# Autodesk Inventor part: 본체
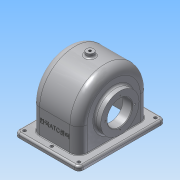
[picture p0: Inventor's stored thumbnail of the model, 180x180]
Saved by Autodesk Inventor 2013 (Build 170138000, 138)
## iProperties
Created: 2015-09
Part Number: 본체
Material: 알루미늄 6061
Document SubType Name: Modeling
Designer: semtle
Density: 2.71 g/cm^3
Mass: 690.142 g
Surface Area: 895.532 cm^2
Volume: 254.665 cm^3
Author: semtle
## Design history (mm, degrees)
sketch "스케치1"
  geometry: L1 (-52, 70)-(52, 70); L2 (52, 70)-(52, -70); L3 (52, -70)-(-52, -70); L4 (-52, -70)-(-52, 70); 1 further point
  constraints: 8 end point, 2 parallel, 1 horizontal, 1 perpendicular
  dimensions: "d0" = 140 distance between parallel lines of L3 L1; "d2" = 70 distance from line of point (0, 0) L1; "d3" = 104 distance between parallel lines of L2 L4; "d4" = 52 distance from line of point (0, 0) L4
extrude "돌출1" new body sketch "스케치1" distance "d5" = 7; taper "d6" = 0 deg
sketch "스케치2"
  geometry: 1 further point
sketch "스케치3"
  geometry: L1 (52, 7)-(-52, 7) reference; L2 (0, 47)-(0, 7); L3 (-52, 0)-(52, 0) reference; 1 further point
  constraints: 2 end point, 1 midpoint, 1 perpendicular
  dimensions: "d9" = 0 distance from line of point (0, 0) L2
sketch "스케치4"
  geometry: L1 (-70, 7)-(70, 7) reference; L2 (-70, 47)-(70, 47); L3 (70, 0)-(-70, 0) reference; L4 (0, 47)-(0, 0); L5 (-57, 47)-(-57, 7); L6 (57, 47)-(57, 7); A1 r 57 centre (0, 47) between (57, 47) and (-57, 47); 4 further points
  constraints: 8 end point, 8 point on line, 2 parallel, 2 perpendicular, 2 point on circle, 2 tangent, 1 centre point, 1 coincident, 1 midpoint
  dimensions: "d11" = 47 distance between parallel lines of L3 L2; "d18" = 57 radius of A1
extrude "돌출2" join sketch "스케치4" stored distance "d15" = 77; taper "d16" = 0 deg
fillet "모깎기1" dims "d19" = 14
fillet "모깎기2" dims "d20" = 7
sketch "스케치5"
  geometry: C1 r 31 at (-47, 0); A1 r 43 centre (-47, 0) between (-47, 43) and (-47, -43) reference; 1 further point
  constraints: 1 centre point, 1 coincident
  dimensions: "d21" = 62 diameter of C1
extrude "돌출3" join sketch "스케치5" distance "d23" = 10; taper "d24" = 0 deg
sketch "스케치6"
  geometry: C1 r 31 at (0, 0) reference; C2 r 20 at (0, 0); 1 further point
  constraints: 1 centre point, 1 coincident
  dimensions: "d25" = 40 diameter of C2
extrude "돌출4" cut sketch "스케치6" distance "d27" = 20; taper "d28" = 0 deg
node "작업 평면1"
node "작업 평면2"
sketch "스케치7"
  geometry: L1 (-14, 0)-(-14, 43) reference; L2 (-14, -40)-(-14, 0) reference; L3 (63, 43)-(63, 0) reference; L4 (63, 0)-(63, -40) reference; L5 (-14, 0)-(63, 0); L6 (0, 57)-(49, 57) reference; L7 (0, 0)-(-14, 0) reference; L8 (-14, 0)-(-14, 0) reference; L9 (0, 0)-(-14, 0) reference; L10 (0, 0)-(0, 0) reference; L11 (-14, -40)-(63, -40); L12 (58.385, 43)-(58.385, 0); L13 (58.385, 0)-(58.385, -35.385); L14 (58.385, -35.385)-(-9.385, -35.385); L15 (-9.385, -35.385)-(-9.385, 0); L16 (-9.385, 0)-(-9.385, 43); A1 r 14 centre (49, 43) between (63, 43) and (49, 57) reference; A2 r 14 centre (0, 43) between (0, 57) and (-14, 43) reference; A3 r 9.967 centre (49, 43) between (58.967, 43) and (49, 52.967); 1 further point
  constraints: 14 end point, 2 point on circle, 1 centre point, 1 parallel, 1 perpendicular, 4 other
  node "투영된 루프1"
sketch "스케치8"
  geometry: C1 r 33 at (47, 0); A1 r 43 centre (47, 0) between (47, -43) and (47, 43) reference; 1 further point
  constraints: 1 centre point, 1 coincident
  dimensions: "d29" = 66 diameter of C1
extrude "돌출5" cut sketch "스케치8" distance "d31" = 5; taper "d32" = 0 deg
sketch "스케치9"
  geometry: C1 r 33 at (0, 0) reference; C2 r 20 at (0, 0); 1 further point
  constraints: 1 centre point, 1 coincident
  dimensions: "d33" = 40 diameter of C2
extrude "돌출6" cut sketch "스케치9" distance "d36" = 16; taper "d37" = 0 deg
sketch "스케치10"
  geometry: L1 (38.5, 80)-(38.5, 14) reference; L2 (-48.5, 78)-(-48.5, 16) reference; L3 (38.5, 47)-(-48.5, 47); L4 (33.5, 27)-(17.5, 27) reference; L5 (-45, 7)-(45, 7) reference; L6 (17.5, 27)-(17.5, 15.895); L7 (33.5, 80)-(33.5, 14) reference; L8 (33.5, 14)-(33.5, 7); L9 (17.5, 15.895)-(33.5, 7); L10 (-28.5, 27)-(-28.5, 67) reference; 1 further point
  constraints: 8 end point, 2 midpoint, 2 perpendicular, 1 point on line
revolve "회전1" sketch "스케치10" stored, may be unused: angle "d38" = 90 deg
sketch "스케치11"
  geometry: L1 (57, 47)-(57, 7) reference; L2 (-57, 7)-(-57, 47) reference; L3 (63, 0)-(63, 7) reference; L4 (-63, 0)-(63, 0) reference; L5 (-63, 7)-(-63, 0) reference; L6 (63, 7)-(-63, 7) reference; L7 (-52, 7)-(-52, 47); L8 (52, 47)-(52, 7); A1 r 57 centre (0, 47) between (57, 47) and (-57, 47) reference; A2 r 52 centre (0, 47) between (52, 47) and (-52, 47); 1 further point
  constraints: 4 end point, 2 point on circle, 1 centre point, 2 other
  dimensions: "d39" = 5 radial gap between concentric circles of A2 A1
extrude "돌출7" cut sketch "스케치11" stored distance "d41" = 67; taper "d42" = 0 deg
fillet "모깎기3" dims "d43" = 9
sketch "스케치12"
  geometry: L1 (33.5, 80)-(33.5, 14) reference; L2 (-45, 7)-(45, 7) reference; L3 (33.5, 27)-(19.199, 27); L4 (19.199, 27)-(19.199, 19); L5 (19.199, 19)-(33.5, 7); L6 (33.5, 27)-(33.5, 7); L7 (-33.5, 27)-(-33.5, 67) reference; L8 (33.5, 47)-(-33.5, 47); 1 further point
  constraints: 10 end point, 2 midpoint, 2 point on line, 1 collinear, 1 parallel, 1 perpendicular
  dimensions: "d44" = 56 diameter of L4.end L8; "d46" = 50 deg angle of L5 L4; "d48" = 40 diameter of L3 L8
revolve "회전2" sketch "스케치12" stored, may be unused: angle "d49" = 90 deg
fillet "모깎기4" dims "d50" = 3
chamfer "모따기1" distance "d51" = 1; stored, may be unused: second distance "d52" = 2, angle "d53" = 45 deg
node "작업 평면3"
sketch "스케치13"
  geometry: C1 r 6 at (0, 0); 1 further point
  constraints: 1 centre point, 1 coincident
  dimensions: "d55" = 12 diameter of C1
extrude "돌출8" join sketch "스케치13" stored distance "d57" = 66; taper "d58" = 0 deg
sketch "스케치14"
  geometry: C1 r 6 at (0, 0) reference; C2 r 2.5 at (0, 0)
  constraints: 1 centre point, 1 coincident
  dimensions: "d59" = 5 diameter of C2
hole "구멍1" sketch "스케치14" at (0, 0) diameter "d61" = 4.134; stored, may be unused: countersink angle "d65" = 90 deg, drill point angle "d67" = 118 deg; dims "d62" = 6, "d63" = 4, "d64" = 2, "d66" = 8
fillet "모깎기5" dims "d68" = 3
fillet "모깎기6" dims "d69" = 1
sketch "스케치15"
  geometry: L1 (-0.387, -13.398)-(49.387, -13.398); L2 (49.387, -13.398)-(49.387, -20.602); L3 (49.387, -20.602)-(-0.387, -20.602); L4 (-0.387, -20.602)-(-0.387, -13.398); L5 (-0.387, -17)-(49.387, -17); L6 (24.5, -13.398)-(24.5, -20.602); L7 (-14, 0)-(-14, -39) reference; L8 (69.5, -47)-(-20.5, -47) reference; 1 further point
  constraints: 4 end point, 4 midpoint, 2 other
  dimensions: "d70" = 38.5 distance between parallel lines of L6 L7; "d71" = 30 distance between parallel lines of L5 L8
feature "엠보싱1" sketch "스케치15" dims "d11" = 47, "d18" = 57, "d72" = 0.5, "d73" = 0
sketch "스케치16"
  geometry: C1 r 2.5 at (-44, 62); C2 r 2.5 at (0, 62); C3 r 2.5 at (44, 62); C4 r 2.5 at (44, -62); C5 r 2.5 at (0, -62); C6 r 2.5 at (-44, -62); 1 further point
  constraints: 6 centre point, 5 equal radius
  dimensions: "d74" = 5 diameter of C1; "d76" = 0 horizontal distance of C6.centre C1.centre; "d77" = 124 distance of C6.centre C1.centre; "d78" = 62 vertical distance of point (0, 0) C1.centre; "d79" = 44 distance of C2.centre C1.centre; "d80" = 44 distance of C3.centre C2.centre; "d81" = 44 distance of C5.centre C6.centre; "d82" = 44 distance of C4.centre C5.centre; "d83" = 124 distance of C4.centre C3.centre; "d84" = 62 vertical distance of point (0, 0) C3.centre; "d85" = 124 distance of C5.centre C2.centre; "d86" = 62 distance of point (0, 0) C2.centre; "d87" = 44 horizontal distance of point (0, 0) C6.centre
extrude "돌출9" cut sketch "스케치16" stored distance "d88" = 66; taper "d89" = 0 deg
sketch "스케치17" dims "d90" = 56
  geometry: L1 (0, 0)-(28, 0); C1 r 21 at (0, 0) reference; C2 r 1.5 at (28, 0); 1 further point
  constraints: 2 coincident, 2 end point, 1 centre point, 1 horizontal, 1 horizontal alignment, 2 other
  dimensions: "d92" = 3 diameter of C2
hole "구멍2" sketch "스케치17" at (28, 0) diameter "d93" = 2.459; stored, may be unused: countersink angle "d97" = 90 deg, drill point angle "d99" = 118 deg; dims "d94" = 7, "d95" = 4, "d96" = 2, "d98" = 9
sketch "스케치18" dims "d103" = 48
  geometry: L1 (0, 0)-(-24, 0); C1 r 21 at (0, 0) reference; C2 r 1.5 at (-24, 0); 1 further point
  constraints: 2 coincident, 2 end point, 1 centre point, 1 horizontal, 1 horizontal alignment, 2 other
  dimensions: "d105" = 3 diameter of C2
hole "구멍3" sketch "스케치18" at (-24, 0) diameter "d106" = 2.459; stored, may be unused: countersink angle "d110" = 90 deg, drill point angle "d112" = 118 deg; dims "d107" = 6, "d108" = 4, "d109" = 2, "d111" = 8
fillet "모깎기7" dims "d116" = 0.5
fillet "모깎기8" dims "d117" = 3
node "솔리드1"
pattern_circular "원형 패턴1" dims angle "d101" = 360 deg
pattern_circular "원형 패턴2" dims angle "d114" = 360 deg
node "투영된 루프2"
other parameters: "d13" = 5, "d17" = 114, "d118" = 67
